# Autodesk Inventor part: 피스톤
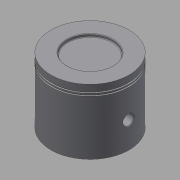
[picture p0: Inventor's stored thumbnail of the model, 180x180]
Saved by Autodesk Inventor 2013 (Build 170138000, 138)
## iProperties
Created: 2016-11
Part Number: 피스톤
Material: 강철, 탄소
Document SubType Name: Modeling
Designer: mduedu
Density: 7.87 g/cm^3
Mass: 273.399 g
Surface Area: 264.986 cm^2
Volume: 34.7394 cm^3
Author: mduedu
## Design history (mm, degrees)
sketch "스케치1"
  geometry: C1 r 30 at (0, 0); 1 further point
  constraints: 1 centre point, 1 coincident
  dimensions: "d0" = 60 diameter of C1
extrude "돌출1" new body sketch "스케치1" distance "d1" = 50; taper "d2" = 0 deg
sketch "스케치2"
  geometry: C1 r 28 at (0, 0); 1 further point
  constraints: 1 centre point, 1 coincident
  dimensions: "d3" = 56 diameter of C1
extrude "돌출2" cut sketch "스케치2" distance "d4" = 45; taper "d5" = 0 deg
sketch "스케치3"
  geometry: L1 (30, 0)-(30, 50) reference; L2 (30, 45)-(29, 45); L3 (29, 45)-(29, 44); L4 (29, 44)-(30, 44); L5 (30, 44)-(30, 45); L6 (30, 43)-(29, 43); L7 (29, 43)-(29, 42); L8 (29, 42)-(30, 42); L9 (30, 42)-(30, 43); L10 (30, 50)-(-30, 50) reference; L11 (0, 50)-(0, 0)
  constraints: 18 end point, 4 parallel, 3 equal length, 3 perpendicular, 2 horizontal, 2 point on line, 1 midpoint
  dimensions: "d6" = 1 distance of L2.start L2.end; "d8" = 5 distance between parallel lines of L10 L2; "d9" = 1 distance between parallel lines of L6 L4
revolve "회전1" sketch "스케치3" stored, may be unused: angle "d10" = 90 deg
node "작업 평면1"
sketch "스케치4"
  geometry: L1 (0, -22.978)-(45, -22.978) reference; L2 (45, -22.978)-(45, 22.978) reference; L3 (45, 22.978)-(0, 22.978) reference; L4 (0, 22.978)-(0, 25.377) reference; L5 (0, 25.377)-(42, 25.377) reference; L6 (42, 25.377)-(42, 24.187) reference; L7 (42, 24.187)-(43, 24.187) reference; L8 (43, 24.187)-(43, 25.377) reference; L9 (43, 25.377)-(44, 25.377) reference; L10 (44, 25.377)-(44, 24.187) reference; L11 (44, 24.187)-(45, 24.187) reference; L12 (45, 24.187)-(45, 25.377) reference; L13 (45, 25.377)-(50, 25.377) reference; L14 (50, 25.377)-(50, -25.377) reference; L15 (50, -25.377)-(45, -25.377) reference; L16 (45, -25.377)-(45, -24.187) reference; L17 (45, -24.187)-(44, -24.187) reference; L18 (44, -24.187)-(44, -25.377) reference; L19 (44, -25.377)-(43, -25.377) reference; L20 (43, -25.377)-(43, -24.187) reference; L21 (43, -24.187)-(42, -24.187) reference; L22 (42, -24.187)-(42, -25.377) reference; L23 (42, -25.377)-(0, -25.377) reference; L24 (0, -25.377)-(0, -22.978) reference; L25 (12.5, 22.978)-(45, 22.978); L26 (45, 22.978)-(45, -22.978); L27 (45, -22.978)-(12.5, -22.978); L28 (12.5, -22.978)-(12.5, 22.978); C1 r 7.5 at (20, 0); C2 r 4 at (20, 0); 1 further point
  constraints: 8 end point, 2 centre point, 2 parallel, 1 coincident, 1 horizontal, 1 horizontal alignment, 1 perpendicular, 1 point on line, 1 tangent
  dimensions: "d12" = 15 diameter of C1; "d13" = 8 diameter of C2; "d14" = 20 distance of point (0, 0) C1.centre
  node "절단 모서리 투영1"
extrude "돌출3" join sketch "스케치4" stored distance "d15" = 11.75; taper "d16" = 0 deg
extrude "돌출4" cut sketch "스케치4" stored distance "d17" = 72; taper "d18" = 0 deg
fillet "모깎기2" dims "d20" = 3
chamfer "모따기1" distance "d21" = 0.5; stored, may be unused: second distance "d22" = 2, angle "d23" = 45 deg
chamfer "모따기2" distance "d24" = 0.5; stored, may be unused: second distance "d25" = 2, angle "d26" = 45 deg
sketch "스케치5"
  geometry: C1 r 17.5 at (0, 0); 1 further point
  constraints: 1 centre point, 1 coincident
  dimensions: "d27" = 35 diameter of C1
extrude "돌출5" cut sketch "스케치5" distance "d28" = 2; taper "d29" = 0 deg
fillet "모깎기3" dims "d30" = 0.5
node "솔리드1"
mirror "대칭1"
other parameters: "d11" = -16
